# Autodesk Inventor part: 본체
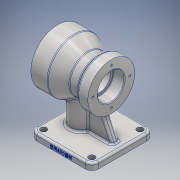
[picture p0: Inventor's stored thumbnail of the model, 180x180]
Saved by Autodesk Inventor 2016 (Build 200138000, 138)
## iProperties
Created: 2019-01
Part Number: 본체
Material: 알루미늄 6061
Document SubType Name: Modeling
Designer: USER
Density: 2.7 g/cm^3
Appearance: 알루미늄 - 평지
Mass: 898.816 g
Surface Area: 600.964 cm^2
Volume: 332.895 cm^3
Author: USER
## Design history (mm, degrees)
sketch "스케치1"
  geometry: L1 (-36, -46)-(36, -46); L2 (46, -36)-(46, 36); L3 (36, 46)-(-36, 46); L4 (-46, 36)-(-46, -36); L5 (-46, -46)-(46, 46); L6 (46, -46)-(-46, 46); C1 r 4.5 at (-36, 36); C2 r 4.5 at (36, 36); C3 r 4.5 at (36, -36); C4 r 4.5 at (-36, -36); A1 r 10 centre (-36, 36) between (-36, 46) and (-46, 36); A2 r 10 centre (36, 36) between (46, 36) and (36, 46); A3 r 10 centre (36, -36) between (36, -46) and (46, -36); A4 r 10 centre (-36, -36) between (-46, -36) and (-36, -46); 1 further point
  constraints: 12 end point, 8 centre point, 8 point on circle, 8 point on line, 8 tangent, 4 coincident, 3 equal radius, 2 midpoint, 2 parallel, 2 perpendicular, 1 horizontal
  dimensions: "d0" = 92 distance of L5.start L6.start; "d1" = 10 radius of A1; "d2" = 9 diameter of C1; "d3" = 9 diameter of C2; "d4" = 9 diameter of C3; "d5" = 9 diameter of C4
extrude "돌출1" new body sketch "스케치1" distance "d6" = 10; taper "d7" = 0 deg
sketch "스케치2"
  geometry: L1 (51, 80)-(-29, 80); L2 (51, 80)-(51, 120); L3 (51, 120)-(26, 120); L4 (26, 120)-(5.215, 108); L5 (5.215, 108)-(-8.126, 108); L6 (-8.126, 108)-(-14, 115); L7 (-14, 115)-(-29, 115); L8 (-29, 115)-(-29, 80); L9 (46, 0)-(46, 10) reference; 1 further point
  constraints: 16 end point, 2 parallel, 2 perpendicular, 1 horizontal, 1 vertical
  dimensions: "d8" = 80 vertical distance of point (0, 0) L1.end; "d9" = 80 diameter of L3 L1; "d10" = 70 diameter of L7 L1; "d11" = 30 deg angle of L5 L4; "d12" = 50 deg angle of L5 L6; "d13" = 56 diameter of L5 L1; "d14" = 80 distance between parallel lines of L8 L2; "d15" = 25 distance of L3.end L2.end; "d16" = 15 distance of L7.end L6.end; "d17" = 5 horizontal distance of L9.start L1.start
revolve "회전1" sketch "스케치2" stored, may be unused: angle "d18" = 90 deg
sketch "스케치3"
  geometry: L1 (-46, 36)-(-46, -36) reference; C1 r 16 at (-16, 0); 1 further point
  constraints: 1 centre point, 1 horizontal alignment
  dimensions: "d19" = 16 radius of C1; "d20" = 30 distance from line of C1.centre L1
extrude "돌출2" join sketch "스케치3" stored distance "d21" = 10; taper "d22" = 0 deg
sketch "스케치4"
  geometry: L1 (0, 10)-(0, 52) reference; L2 (-36, 10)-(36, 10) reference; L3 (-36, 10)-(-46, 10) reference; L4 (-36, 10)-(-25.393, 32.746); L5 (-46, 0)-(-46, 10) reference; 1 further point
  constraints: 2 end point, 1 point on line
  dimensions: "d23" = 25 deg angle of L5 L4; "d24" = 10 distance of L3.end L4.start
feature "리브1" sketch "스케치4" dims "d25" = 1, "d26" = 10, "d27" = 0, "d28" = 0, "d29" = 1, "d30" = 1
sketch "스케치5"
  geometry: L1 (51, 40)-(51, 120) reference; L2 (-29, 45)-(-29, 115) reference; L3 (51, 80)-(-29, 80); L4 (51, 106)-(32, 106); L5 (31, 105)-(31, 96); L6 (31, 96)-(-12, 96); L7 (-14, 45.359)-(-14, 115) reference; L8 (-12, 96)-(-12, 99.4); L9 (-12.6, 100)-(-29, 100); L10 (51, 106)-(51, 80); L11 (-29, 100)-(-29, 80); A1 r 1 centre (32, 105) between (32, 106) and (31, 105); A2 r 0.6 centre (-12.6, 99.4) between (-12, 99.4) and (-12.6, 100); 3 further points
  constraints: 16 end point, 6 perpendicular, 6 point on line, 4 point on circle, 4 tangent, 2 centre point, 2 midpoint, 1 collinear, 1 horizontal
  dimensions: "d31" = 80 vertical distance of point (0, 0) L3.end; "d32" = 52 diameter of L4 L3; "d34" = 40 diameter of L9 L3; "d35" = 20 distance of L4.start point (31, 106); "d36" = 17 distance of point (-12, 100) L9.end; "d37" = 32 diameter of L6 L3; "d38" = 1 radius of A1; "d39" = 0.6 radius of A2
revolve "회전2" sketch "스케치5" stored, may be unused: angle "d40" = 90 deg
sketch "스케치6"
  geometry: C1 r 40 at (0, 0) reference; 2 further points
  constraints: 1 horizontal alignment
  dimensions: "d41" = 33 distance of C1.centre point (33, 0)
hole "구멍1" sketch "스케치6" at (33, 0) diameter "d42" = 3.242; stored, may be unused: countersink angle "d46" = 90 deg, drill point angle "d48" = 118 deg; dims "d43" = 9, "d44" = 4, "d45" = 2, "d47" = 11
sketch "스케치7"
  geometry: C1 r 35 at (0, 0) reference; 2 further points
  constraints: 1 horizontal alignment
  dimensions: "d52" = 27.5 distance of C1.centre point (-27.5, 0)
hole "구멍2" sketch "스케치7" at (-27.5, 0) diameter "d53" = 3.242; stored, may be unused: countersink angle "d57" = 90 deg, drill point angle "d59" = 118 deg; dims "d54" = 9, "d55" = 4, "d56" = 2, "d58" = 11
chamfer "모따기1" distance "d63" = 1; stored, may be unused: second distance "d64" = 2, angle "d65" = 45 deg
fillet "모깎기1" dims "d66" = 3
fillet "모깎기2" dims "d67" = 3
fillet "모깎기3" dims "d68" = 3
sketch "스케치8"
  geometry: L1 (82, 0)-(72, 0) reference; L2 (0, 0)-(-10, 0) reference; 2 further points
  constraints: 1 other
  dimensions: "d69" = 4 vertical distance of L1.start point (36, 4); "d70" = 46 horizontal distance of point (36, 4) L2.end
feature "엠보싱1" sketch "스케치8" dims "d8" = 80, "d9" = 80, "d10" = 70, "d11" = 30 deg, "d12" = 50 deg, "d13" = 56, "d14" = 80, "d15" = 25, "d16" = 15, "d17" = 5, "d71" = 0.5, "d72" = 0
node "솔리드1"
pattern_circular "원형 패턴1" dims angle "d50" = 360 deg
pattern_circular "원형 패턴2" dims angle "d61" = 360 deg
